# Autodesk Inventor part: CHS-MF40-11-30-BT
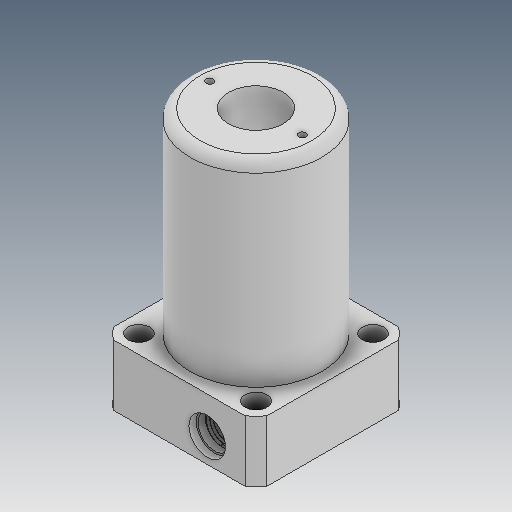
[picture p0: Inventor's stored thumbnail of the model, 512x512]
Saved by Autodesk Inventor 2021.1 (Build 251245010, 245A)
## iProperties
Created: 2019-04
Part Number: CHS-MF40-11-30-BT
Material: Ogólny
Document SubType Name: Modeling
Designer: user
Density: 1 g/cm^3
Appearance: Domyślna
Author: user
Revision Number: ÈÎºÎ
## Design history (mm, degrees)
feature "ÊäÈë1"
node "Bryła1"
